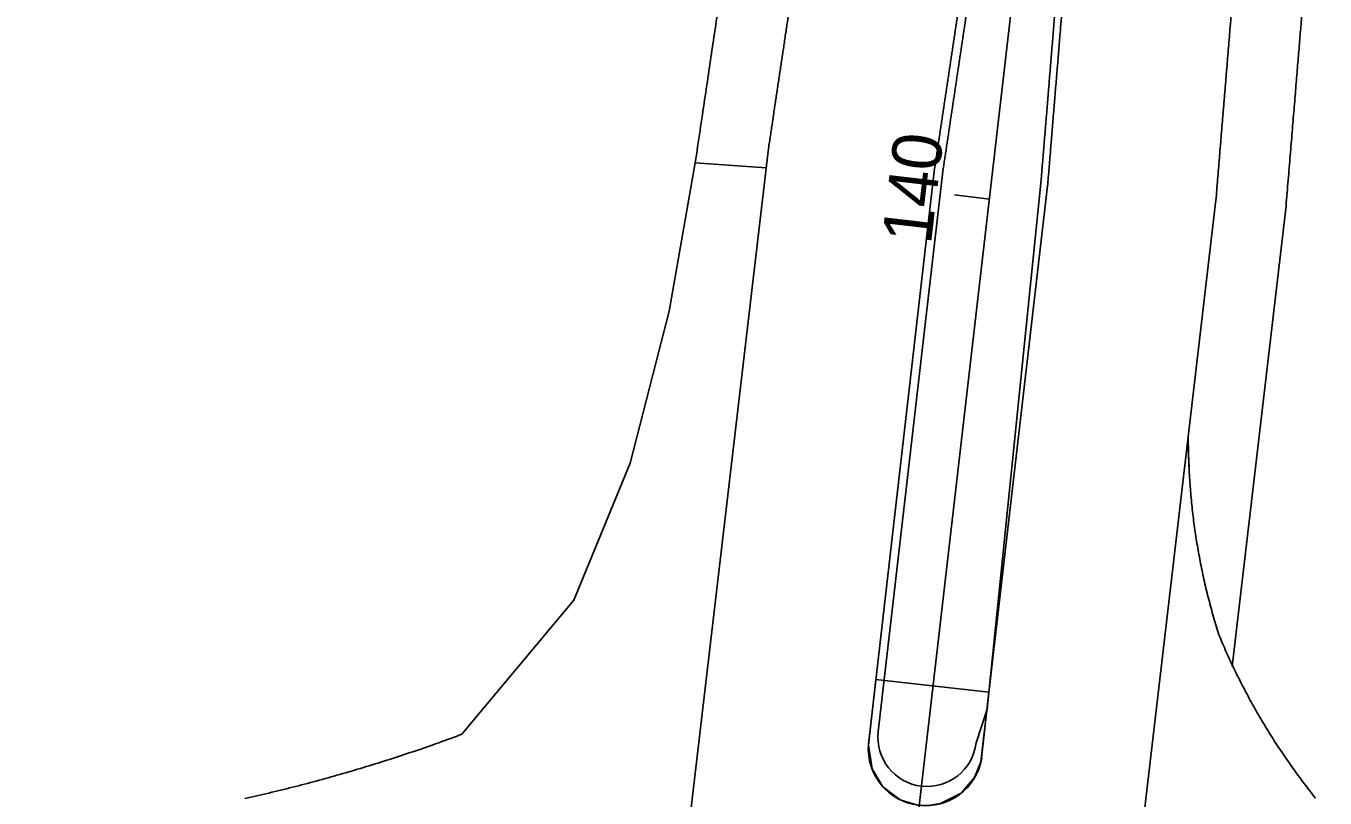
# Model space of a CAD drawing. Extents: x 2318076 to 2324211, y 613525 to 629939.
# Drawn here: x 2320485.2 to 2320669.8, y 628482.6 to 628592.3 of the extents above; entities that cross this region are included whole.
import ezdxf

# ---------------------------------------------------------------- set-up
doc = ezdxf.new("R2010")
doc.units = 0
for name, color, linetype in [('Default', 7, 'Continuous'), ('GE_P_CL_50', 7, 'Continuous'), ('PM_P_Island', 7, 'Continuous'), ('PV_P_EOP', 7, 'Continuous'), ('PV_P_Shoulder', 7, 'Continuous'), ('PV_X_Curb', 7, 'Continuous'), ('RS_Raster1', 7, 'Continuous')]:
    doc.layers.add(name, color=color, linetype=linetype)

msp = doc.modelspace()

# ---------------------------------------------------------------- linework, layer by layer
at = {"layer": 'Default'}
msp.add_line((2320580.32, 628572.84), (2320590.42, 628572.16), dxfattribs=at)
at = {"layer": 'GE_P_CL_50'}
msp.add_line((2320622.12, 628567.72), (2320617.15, 628568.29), dxfattribs=at)
msp.add_lwpolyline([(2320485.22, 627375.57), (2320502.11, 627520.92), (2320519.22, 627676.47), (2320531.82, 627783.89), (2320546.8, 627927.12), (2320554.45, 627991.34), (2320572.51, 628138.41), (2320649.52, 628804.84), (2320678.77, 629064.5), (2320690.76, 629163.78), (2320713.75, 629362.45), (2320725.26, 629461.78), (2320736.97, 629561.09), (2320748.4, 629660.43), (2320759.09, 629759.86), (2320769.62, 629859.3), (2320777.51, 629931.12), (2320778.25, 629937.84)], dxfattribs=at)
at = {"layer": 'PM_P_Island'}
msp.add_lwpolyline([(2320622.04, 628497.59), (2320606, 628499.42), (2320604.93, 628490.08), (2320605.45, 628486.7), (2320606.99, 628484.17), (2320609.45, 628482.31), (2320611.9, 628481.55), (2320612.52, 628481.49), (2320613.49, 628481.49), (2320615.17, 628481.76), (2320618.12, 628483.27), (2320620.03, 628485.47), (2320620.95, 628487.79)], close=True, dxfattribs=at)
at = {"layer": 'PV_P_EOP'}
for p, q in [((2320590.74, 628574.92), (2320513.05, 627912.02)), ((2320604.94, 628490.2), (2320614.34, 628572.05)), ((2320620.93, 628487.71), (2320630.4, 628569.61)), ((2320576.7, 627905.37), (2320654.32, 628567.57))]:
    msp.add_line(p, q, dxfattribs=at)
for points in [[(2320650.31, 628533.42), (2320650.52, 628529.13), (2320650.53, 628528.81), (2320650.55, 628528.48), (2320650.57, 628528.15), (2320650.59, 628527.83), (2320650.61, 628527.5), (2320650.64, 628527.18), (2320650.66, 628526.85), (2320650.68, 628526.53), (2320650.71, 628526.2), (2320650.74, 628525.88), (2320650.77, 628525.55), (2320650.8, 628525.23), (2320650.83, 628524.9), (2320650.86, 628524.58), (2320650.89, 628524.26), (2320650.92, 628523.93), (2320650.96, 628523.61), (2320651, 628523.28), (2320651.03, 628522.96), (2320651.07, 628522.64), (2320651.11, 628522.31), (2320651.15, 628521.99), (2320651.19, 628521.67), (2320651.24, 628521.34), (2320651.28, 628521.02), (2320651.33, 628520.7), (2320651.37, 628520.37), (2320651.42, 628520.05), (2320651.47, 628519.73), (2320651.52, 628519.41), (2320651.57, 628519.09), (2320651.62, 628518.76), (2320651.68, 628518.44), (2320651.73, 628518.12), (2320651.79, 628517.8), (2320651.84, 628517.48), (2320651.9, 628517.16), (2320651.96, 628516.84), (2320652.02, 628516.52), (2320652.08, 628516.2), (2320652.14, 628515.88), (2320652.21, 628515.56), (2320652.27, 628515.24), (2320652.34, 628514.92), (2320652.4, 628514.6), (2320652.47, 628514.28), (2320652.54, 628513.96), (2320652.61, 628513.64), (2320652.68, 628513.33), (2320652.76, 628513.01), (2320652.83, 628512.69), (2320652.9, 628512.37), (2320652.98, 628512.06), (2320653.06, 628511.74), (2320653.13, 628511.42), (2320653.21, 628511.11), (2320653.29, 628510.79), (2320653.38, 628510.48), (2320653.46, 628510.16), (2320653.54, 628509.85), (2320653.63, 628509.53), (2320653.71, 628509.22), (2320653.8, 628508.9), (2320653.89, 628508.59), (2320653.98, 628508.28), (2320654.07, 628507.96), (2320654.16, 628507.65), (2320654.25, 628507.34), (2320654.34, 628507.03), (2320654.44, 628506.71), (2320654.54, 628506.4), (2320654.63, 628506.09), (2320654.73, 628505.78)], [(2320654.73, 628505.78), (2320654.86, 628505.47), (2320654.99, 628505.16), (2320655.12, 628504.86), (2320655.25, 628504.55), (2320655.38, 628504.24), (2320655.52, 628503.94), (2320655.65, 628503.63), (2320655.79, 628503.32), (2320655.92, 628503.02), (2320656.06, 628502.71), (2320656.2, 628502.41), (2320656.34, 628502.11), (2320656.48, 628501.8), (2320656.62, 628501.5), (2320656.77, 628501.2), (2320656.91, 628500.9), (2320657.06, 628500.6), (2320657.2, 628500.3), (2320657.35, 628500), (2320657.5, 628499.7), (2320657.65, 628499.4), (2320657.8, 628499.1), (2320657.95, 628498.8), (2320658.1, 628498.51), (2320658.26, 628498.21), (2320658.41, 628497.91), (2320658.57, 628497.62), (2320658.73, 628497.32), (2320658.88, 628497.03), (2320659.04, 628496.73), (2320659.2, 628496.44), (2320659.36, 628496.15), (2320659.52, 628495.85), (2320659.69, 628495.56), (2320659.85, 628495.27), (2320660.02, 628494.98), (2320660.18, 628494.69), (2320660.35, 628494.4), (2320660.52, 628494.11), (2320660.69, 628493.82), (2320660.86, 628493.54), (2320661.03, 628493.25), (2320661.2, 628492.96), (2320661.37, 628492.68), (2320661.55, 628492.39), (2320661.72, 628492.11), (2320661.9, 628491.82), (2320662.08, 628491.54), (2320662.25, 628491.26), (2320662.43, 628490.98), (2320662.61, 628490.69), (2320662.79, 628490.41), (2320662.98, 628490.13), (2320663.16, 628489.85), (2320663.34, 628489.57), (2320663.53, 628489.3), (2320663.71, 628489.02), (2320663.9, 628488.74), (2320664.09, 628488.47), (2320664.28, 628488.19), (2320664.47, 628487.91), (2320664.66, 628487.64), (2320664.85, 628487.37), (2320665.04, 628487.09), (2320665.24, 628486.82), (2320665.43, 628486.55), (2320665.63, 628486.28), (2320665.82, 628486.01), (2320666.02, 628485.74), (2320666.22, 628485.47), (2320666.42, 628485.2), (2320666.62, 628484.93), (2320666.82, 628484.67), (2320667.02, 628484.4), (2320667.22, 628484.14), (2320667.43, 628483.87), (2320667.63, 628483.61), (2320667.84, 628483.35), (2320668.04, 628483.08), (2320668.25, 628482.82), (2320668.46, 628482.56)]]:
    msp.add_lwpolyline(points, dxfattribs=at)
msp.add_arc((2320613.03, 628489.59), 8.12, 175.7115, 350.2041, dxfattribs=at)
for points in [[(2320590.74, 628574.92), (2320590.87, 628575.82), (2320591.01, 628576.72), (2320591.14, 628577.62), (2320591.28, 628578.53), (2320591.41, 628579.43), (2320591.54, 628580.33), (2320591.68, 628581.23), (2320591.81, 628582.13), (2320591.95, 628583.04), (2320592.08, 628583.94), (2320592.22, 628584.84), (2320592.35, 628585.74), (2320592.49, 628586.64), (2320592.62, 628587.55), (2320592.76, 628588.45), (2320592.89, 628589.35), (2320593.02, 628590.25), (2320593.16, 628591.15), (2320593.29, 628592.06), (2320593.43, 628592.96), (2320593.56, 628593.86), (2320593.7, 628594.76), (2320593.83, 628595.66), (2320593.97, 628596.57), (2320594.1, 628597.47), (2320594.23, 628598.37), (2320594.37, 628599.27), (2320594.5, 628600.17), (2320594.64, 628601.07), (2320594.77, 628601.98), (2320594.91, 628602.88), (2320595.04, 628603.78), (2320595.18, 628604.68), (2320595.31, 628605.58), (2320595.44, 628606.49), (2320595.58, 628607.39), (2320595.71, 628608.29), (2320595.85, 628609.19), (2320595.98, 628610.09), (2320596.12, 628611), (2320596.25, 628611.9), (2320596.39, 628612.8), (2320596.52, 628613.7), (2320596.65, 628614.6), (2320596.79, 628615.51), (2320596.92, 628616.41), (2320597.06, 628617.31), (2320597.19, 628618.21), (2320597.33, 628619.11), (2320597.46, 628620.02), (2320597.6, 628620.92), (2320597.73, 628621.82), (2320597.86, 628622.72), (2320598, 628623.62), (2320598.13, 628624.53), (2320598.27, 628625.43), (2320598.4, 628626.33), (2320598.54, 628627.23), (2320598.67, 628628.13), (2320598.81, 628629.03), (2320598.94, 628629.94), (2320599.07, 628630.84), (2320599.21, 628631.74), (2320599.34, 628632.64), (2320599.48, 628633.54), (2320599.61, 628634.45), (2320599.75, 628635.35), (2320599.88, 628636.25), (2320600.02, 628637.15), (2320600.15, 628638.05), (2320600.28, 628638.96), (2320600.42, 628639.86), (2320600.55, 628640.76), (2320600.69, 628641.66)], [(2320654.32, 628567.57), (2320654.39, 628568.48), (2320654.46, 628569.39), (2320654.54, 628570.3), (2320654.61, 628571.21), (2320654.69, 628572.12), (2320654.76, 628573.02), (2320654.84, 628573.93), (2320654.91, 628574.84), (2320654.99, 628575.75), (2320655.06, 628576.66), (2320655.14, 628577.57), (2320655.21, 628578.48), (2320655.29, 628579.39), (2320655.36, 628580.3), (2320655.44, 628581.2), (2320655.51, 628582.11), (2320655.59, 628583.02), (2320655.66, 628583.93), (2320655.74, 628584.84), (2320655.81, 628585.75), (2320655.89, 628586.66), (2320655.96, 628587.57), (2320656.04, 628588.48), (2320656.11, 628589.38), (2320656.18, 628590.29), (2320656.26, 628591.2), (2320656.33, 628592.11), (2320656.41, 628593.02), (2320656.48, 628593.93), (2320656.56, 628594.84), (2320656.63, 628595.75), (2320656.71, 628596.65), (2320656.78, 628597.56), (2320656.86, 628598.47), (2320656.93, 628599.38), (2320657.01, 628600.29), (2320657.08, 628601.2), (2320657.16, 628602.11), (2320657.23, 628603.02), (2320657.31, 628603.93), (2320657.38, 628604.83), (2320657.46, 628605.74), (2320657.53, 628606.65), (2320657.61, 628607.56), (2320657.68, 628608.47), (2320657.76, 628609.38), (2320657.83, 628610.29), (2320657.91, 628611.2), (2320657.98, 628612.1), (2320658.05, 628613.01), (2320658.13, 628613.92), (2320658.2, 628614.83), (2320658.28, 628615.74), (2320658.35, 628616.65), (2320658.43, 628617.56), (2320658.5, 628618.47), (2320658.58, 628619.38), (2320658.65, 628620.28), (2320658.73, 628621.19), (2320658.8, 628622.1), (2320658.88, 628623.01), (2320658.95, 628623.92), (2320659.03, 628624.83), (2320659.1, 628625.74), (2320659.18, 628626.65), (2320659.25, 628627.55), (2320659.33, 628628.46), (2320659.4, 628629.37), (2320659.48, 628630.28), (2320659.55, 628631.19), (2320659.63, 628632.1), (2320659.7, 628633.01), (2320659.77, 628633.92), (2320659.85, 628634.83)], [(2320614.34, 628572.05), (2320614.46, 628572.85), (2320614.58, 628573.65), (2320614.7, 628574.46), (2320614.82, 628575.26), (2320614.94, 628576.06), (2320615.06, 628576.86), (2320615.18, 628577.67), (2320615.3, 628578.47), (2320615.42, 628579.27), (2320615.54, 628580.07), (2320615.66, 628580.87), (2320615.78, 628581.68), (2320615.9, 628582.48), (2320616.02, 628583.28), (2320616.14, 628584.08), (2320616.26, 628584.89), (2320616.38, 628585.69), (2320616.5, 628586.49), (2320616.62, 628587.29), (2320616.74, 628588.1), (2320616.86, 628588.9), (2320616.98, 628589.7), (2320617.1, 628590.5), (2320617.22, 628591.31), (2320617.34, 628592.11), (2320617.46, 628592.91), (2320617.58, 628593.71), (2320617.69, 628594.51), (2320617.81, 628595.32), (2320617.93, 628596.12), (2320618.05, 628596.92), (2320618.17, 628597.72), (2320618.29, 628598.53), (2320618.41, 628599.33), (2320618.53, 628600.13), (2320618.65, 628600.93), (2320618.77, 628601.74), (2320618.89, 628602.54), (2320619.01, 628603.34), (2320619.13, 628604.14), (2320619.25, 628604.95), (2320619.37, 628605.75), (2320619.49, 628606.55), (2320619.61, 628607.35), (2320619.73, 628608.15), (2320619.85, 628608.96), (2320619.97, 628609.76), (2320620.09, 628610.56), (2320620.21, 628611.36), (2320620.33, 628612.17), (2320620.45, 628612.97), (2320620.57, 628613.77), (2320620.69, 628614.57), (2320620.81, 628615.38), (2320620.93, 628616.18), (2320621.05, 628616.98), (2320621.17, 628617.78), (2320621.29, 628618.58), (2320621.41, 628619.39), (2320621.53, 628620.19), (2320621.65, 628620.99), (2320621.77, 628621.79), (2320621.89, 628622.6), (2320622.01, 628623.4), (2320622.13, 628624.2), (2320622.25, 628625), (2320622.37, 628625.81), (2320622.49, 628626.61), (2320622.61, 628627.41), (2320622.73, 628628.21), (2320622.85, 628629.02), (2320622.97, 628629.82), (2320623.21, 628631.42)], [(2320630.4, 628569.61), (2320630.46, 628570.42), (2320630.53, 628571.23), (2320630.6, 628572.04), (2320630.66, 628572.85), (2320630.73, 628573.66), (2320630.8, 628574.47), (2320630.86, 628575.27), (2320630.93, 628576.08), (2320630.99, 628576.89), (2320631.06, 628577.7), (2320631.13, 628578.51), (2320631.19, 628579.32), (2320631.26, 628580.13), (2320631.33, 628580.93), (2320631.39, 628581.74), (2320631.46, 628582.55), (2320631.52, 628583.36), (2320631.59, 628584.17), (2320631.66, 628584.98), (2320631.72, 628585.79), (2320631.79, 628586.59), (2320631.86, 628587.4), (2320631.92, 628588.21), (2320631.99, 628589.02), (2320632.05, 628589.83), (2320632.12, 628590.64), (2320632.19, 628591.44), (2320632.25, 628592.25), (2320632.32, 628593.06), (2320632.38, 628593.87), (2320632.45, 628594.68), (2320632.52, 628595.49), (2320632.58, 628596.3), (2320632.65, 628597.1), (2320632.72, 628597.91), (2320632.78, 628598.72), (2320632.85, 628599.53), (2320632.91, 628600.34), (2320632.98, 628601.15), (2320633.05, 628601.96), (2320633.11, 628602.76), (2320633.18, 628603.57), (2320633.25, 628604.38), (2320633.31, 628605.19), (2320633.38, 628606), (2320633.44, 628606.81), (2320633.51, 628607.62), (2320633.58, 628608.42), (2320633.64, 628609.23), (2320633.71, 628610.04), (2320633.78, 628610.85), (2320633.84, 628611.66), (2320633.91, 628612.47), (2320633.97, 628613.28), (2320634.04, 628614.08), (2320634.11, 628614.89), (2320634.17, 628615.7), (2320634.24, 628616.51), (2320634.31, 628617.32), (2320634.37, 628618.13), (2320634.44, 628618.94), (2320634.5, 628619.74), (2320634.57, 628620.55), (2320634.64, 628621.36), (2320634.7, 628622.17), (2320634.77, 628622.98), (2320634.84, 628623.79), (2320634.9, 628624.6), (2320634.97, 628625.4), (2320635.03, 628626.21), (2320635.1, 628627.02), (2320635.17, 628627.83), (2320635.3, 628629.45)]]:
    msp.add_spline(points, degree=3, dxfattribs=at)
at = {"layer": 'PV_P_Shoulder'}
msp.add_line((2320656.61, 628501.27), (2320664.28, 628566.75), dxfattribs=at)
for points in [[(2320580.32, 628572.84), (2320584.16, 628598.64), (2320587.48, 628620.89), (2320590.8, 628643.14)], [(2320664.28, 628566.75), (2320666.13, 628589.17), (2320667.97, 628611.59), (2320669.82, 628634.01)]]:
    msp.add_open_spline(points, degree=2, dxfattribs=at)
at = {"layer": 'PV_X_Curb'}
msp.add_line((2320606.32, 628492), (2320615.57, 628572.05), dxfattribs=at)
msp.add_lwpolyline([(2320620.23, 628490.39), (2320621.8, 628495.17), (2320629.48, 628570.44)], dxfattribs=at)
for start, end in [(173.4084, 263.4084), (263.4084, 353.4084)]:
    msp.add_arc((2320613.28, 628491.2), 7, start, end, dxfattribs=at)
for points in [[(2320615.57, 628572.05), (2320615.69, 628572.85), (2320615.81, 628573.65), (2320615.93, 628574.46), (2320616.05, 628575.26), (2320616.17, 628576.06), (2320616.29, 628576.86), (2320616.41, 628577.67), (2320616.53, 628578.47), (2320616.65, 628579.27), (2320616.77, 628580.07), (2320616.89, 628580.87), (2320617.01, 628581.68), (2320617.13, 628582.48), (2320617.25, 628583.28), (2320617.37, 628584.08), (2320617.49, 628584.89), (2320617.61, 628585.69), (2320617.73, 628586.49), (2320617.85, 628587.29), (2320617.97, 628588.1), (2320618.09, 628588.9), (2320618.21, 628589.7), (2320618.33, 628590.5), (2320618.45, 628591.31), (2320618.57, 628592.11), (2320618.69, 628592.91), (2320618.81, 628593.71), (2320618.93, 628594.51), (2320619.05, 628595.32), (2320619.17, 628596.12), (2320619.29, 628596.92), (2320619.41, 628597.72), (2320619.53, 628598.53), (2320619.65, 628599.33), (2320619.77, 628600.13), (2320619.89, 628600.93), (2320620.01, 628601.74), (2320620.13, 628602.54), (2320620.25, 628603.34), (2320620.37, 628604.14), (2320620.49, 628604.95), (2320620.61, 628605.75), (2320620.73, 628606.55), (2320620.85, 628607.35), (2320620.97, 628608.15), (2320621.09, 628608.96), (2320621.21, 628609.76), (2320621.33, 628610.56), (2320621.45, 628611.36), (2320621.57, 628612.17), (2320621.69, 628612.97), (2320621.81, 628613.77), (2320621.93, 628614.57), (2320622.05, 628615.38), (2320622.17, 628616.18), (2320622.29, 628616.98), (2320622.41, 628617.78), (2320622.53, 628618.58), (2320622.65, 628619.39), (2320622.77, 628620.19), (2320622.89, 628620.99), (2320623.01, 628621.79), (2320623.13, 628622.6), (2320623.25, 628623.4), (2320623.37, 628624.2), (2320623.49, 628625), (2320623.61, 628625.81), (2320623.73, 628626.61), (2320623.85, 628627.41), (2320623.97, 628628.21), (2320624.09, 628629.02), (2320624.21, 628629.82), (2320623.32, 628632.14), (2320623.12, 628630.84)], [(2320629.48, 628570.44), (2320629.55, 628571.25), (2320629.61, 628572.06), (2320629.68, 628572.87), (2320629.75, 628573.68), (2320629.81, 628574.48), (2320629.88, 628575.29), (2320629.94, 628576.1), (2320630.01, 628576.91), (2320630.08, 628577.72), (2320630.14, 628578.53), (2320630.21, 628579.34), (2320630.28, 628580.14), (2320630.34, 628580.95), (2320630.41, 628581.76), (2320630.47, 628582.57), (2320630.54, 628583.38), (2320630.61, 628584.19), (2320630.67, 628585), (2320630.74, 628585.8), (2320630.8, 628586.61), (2320630.87, 628587.42), (2320630.94, 628588.23), (2320631, 628589.04), (2320631.07, 628589.85), (2320631.14, 628590.66), (2320631.2, 628591.46), (2320631.27, 628592.27), (2320631.33, 628593.08), (2320631.4, 628593.89), (2320631.47, 628594.7), (2320631.53, 628595.51), (2320631.6, 628596.32), (2320631.67, 628597.12), (2320631.73, 628597.93), (2320631.8, 628598.74), (2320631.86, 628599.55), (2320631.93, 628600.36), (2320632, 628601.17), (2320632.06, 628601.98), (2320632.13, 628602.78), (2320632.2, 628603.59), (2320632.26, 628604.4), (2320632.33, 628605.21), (2320632.39, 628606.02), (2320632.46, 628606.83), (2320632.53, 628607.64), (2320632.59, 628608.44), (2320632.66, 628609.25), (2320632.73, 628610.06), (2320632.79, 628610.87), (2320632.86, 628611.68), (2320632.92, 628612.49), (2320632.99, 628613.3), (2320633.06, 628614.1), (2320633.12, 628614.91), (2320633.19, 628615.72), (2320633.26, 628616.53), (2320633.32, 628617.34), (2320633.39, 628618.15), (2320633.45, 628618.95), (2320633.52, 628619.76), (2320633.59, 628620.57), (2320633.65, 628621.38), (2320633.72, 628622.19), (2320633.79, 628623), (2320633.85, 628623.81), (2320633.92, 628624.61), (2320633.98, 628625.42), (2320634.05, 628626.23), (2320634.12, 628627.04), (2320634.18, 628627.85), (2320634.25, 628628.66), (2320634.38, 628630.27)]]:
    msp.add_spline(points, degree=3, dxfattribs=at)
at = {"layer": 'RS_Raster1'}
for points in [[(2320547.18, 628491.63), (2320563.05, 628510.71), (2320571.06, 628530.15), (2320576.64, 628551.77), (2320580.32, 628572.84)], [(2320650.37, 628533.94), (2320650.43, 628531.41), (2320650.44, 628531.09), (2320650.45, 628530.76), (2320650.46, 628530.43), (2320650.47, 628530.11), (2320650.49, 628529.78), (2320650.5, 628529.46), (2320650.52, 628529.13), (2320650.53, 628528.81), (2320650.55, 628528.48), (2320650.57, 628528.15), (2320650.59, 628527.83), (2320650.61, 628527.5), (2320650.64, 628527.18), (2320650.66, 628526.85), (2320650.68, 628526.53), (2320650.71, 628526.2), (2320650.74, 628525.88), (2320650.77, 628525.55), (2320650.8, 628525.23), (2320650.83, 628524.9), (2320650.86, 628524.58), (2320650.89, 628524.26), (2320650.92, 628523.93), (2320650.96, 628523.61), (2320651, 628523.28), (2320651.03, 628522.96), (2320651.07, 628522.64), (2320651.11, 628522.31), (2320651.15, 628521.99), (2320651.19, 628521.67), (2320651.24, 628521.34), (2320651.28, 628521.02), (2320651.33, 628520.7), (2320651.37, 628520.37), (2320651.42, 628520.05), (2320651.47, 628519.73), (2320651.52, 628519.41), (2320651.57, 628519.09), (2320651.62, 628518.76), (2320651.68, 628518.44), (2320651.73, 628518.12), (2320651.79, 628517.8), (2320651.84, 628517.48), (2320651.9, 628517.16), (2320651.96, 628516.84), (2320652.02, 628516.52), (2320652.08, 628516.2), (2320652.14, 628515.88), (2320652.21, 628515.56), (2320652.27, 628515.24), (2320652.34, 628514.92), (2320652.4, 628514.6), (2320652.47, 628514.28), (2320652.54, 628513.96), (2320652.61, 628513.64), (2320652.68, 628513.33), (2320652.76, 628513.01), (2320652.83, 628512.69), (2320652.9, 628512.37), (2320652.98, 628512.06), (2320653.06, 628511.74), (2320653.13, 628511.42), (2320653.21, 628511.11), (2320653.29, 628510.79), (2320653.38, 628510.48), (2320653.46, 628510.16), (2320653.54, 628509.85), (2320653.63, 628509.53), (2320653.71, 628509.22), (2320653.8, 628508.9), (2320653.89, 628508.59), (2320653.98, 628508.28), (2320654.07, 628507.96), (2320654.16, 628507.65), (2320654.25, 628507.34), (2320654.34, 628507.03), (2320654.44, 628506.71), (2320654.54, 628506.4), (2320654.63, 628506.09), (2320654.73, 628505.78)], [(2320654.73, 628505.78), (2320654.86, 628505.47), (2320654.99, 628505.16), (2320655.12, 628504.86), (2320655.25, 628504.55), (2320655.38, 628504.24), (2320655.52, 628503.94), (2320655.65, 628503.63), (2320655.79, 628503.32), (2320655.92, 628503.02), (2320656.06, 628502.71), (2320656.2, 628502.41), (2320656.34, 628502.11), (2320656.48, 628501.8), (2320656.62, 628501.5), (2320656.77, 628501.2), (2320656.91, 628500.9), (2320657.06, 628500.6), (2320657.2, 628500.3), (2320657.35, 628500), (2320657.5, 628499.7), (2320657.65, 628499.4), (2320657.8, 628499.1), (2320657.95, 628498.8), (2320658.1, 628498.51), (2320658.26, 628498.21), (2320658.41, 628497.91), (2320658.57, 628497.62), (2320658.73, 628497.32), (2320658.88, 628497.03), (2320659.04, 628496.73), (2320659.2, 628496.44), (2320659.36, 628496.15), (2320659.52, 628495.85), (2320659.69, 628495.56), (2320659.85, 628495.27), (2320660.02, 628494.98), (2320660.18, 628494.69), (2320660.35, 628494.4), (2320660.52, 628494.11), (2320660.69, 628493.82), (2320660.86, 628493.54), (2320661.03, 628493.25), (2320661.2, 628492.96), (2320661.37, 628492.68), (2320661.55, 628492.39), (2320661.72, 628492.11), (2320661.9, 628491.82), (2320662.08, 628491.54), (2320662.25, 628491.26), (2320662.43, 628490.98), (2320662.61, 628490.69), (2320662.79, 628490.41), (2320662.98, 628490.13), (2320663.16, 628489.85), (2320663.34, 628489.57), (2320663.53, 628489.3), (2320663.71, 628489.02), (2320663.9, 628488.74), (2320664.09, 628488.47), (2320664.28, 628488.19), (2320664.47, 628487.91), (2320664.66, 628487.64), (2320664.85, 628487.37), (2320665.04, 628487.09), (2320665.24, 628486.82), (2320665.43, 628486.55), (2320665.63, 628486.28), (2320665.82, 628486.01), (2320666.02, 628485.74), (2320666.22, 628485.47), (2320666.42, 628485.2), (2320666.62, 628484.93), (2320666.82, 628484.67), (2320667.02, 628484.4), (2320667.22, 628484.14), (2320667.43, 628483.87), (2320667.63, 628483.61), (2320667.84, 628483.35), (2320668.04, 628483.08), (2320668.25, 628482.82), (2320668.46, 628482.56)], [(2320516.33, 628482.49), (2320516.75, 628482.58), (2320517.18, 628482.68), (2320517.6, 628482.77), (2320518.03, 628482.87), (2320518.45, 628482.97), (2320518.87, 628483.07), (2320519.3, 628483.17), (2320519.72, 628483.27), (2320520.15, 628483.37), (2320520.57, 628483.47), (2320520.99, 628483.57), (2320521.41, 628483.67), (2320521.84, 628483.78), (2320522.26, 628483.88), (2320522.68, 628483.99), (2320523.1, 628484.1), (2320523.53, 628484.2), (2320523.95, 628484.31), (2320524.37, 628484.42), (2320524.79, 628484.53), (2320525.21, 628484.64), (2320525.63, 628484.75), (2320526.05, 628484.86), (2320526.47, 628484.98), (2320526.89, 628485.09), (2320527.31, 628485.2), (2320527.73, 628485.32), (2320528.15, 628485.44), (2320528.57, 628485.55), (2320528.99, 628485.67), (2320529.41, 628485.79), (2320529.83, 628485.91), (2320530.24, 628486.03), (2320530.66, 628486.15), (2320531.08, 628486.27), (2320531.5, 628486.39), (2320531.92, 628486.52), (2320532.33, 628486.64), (2320532.75, 628486.77), (2320533.17, 628486.89), (2320533.58, 628487.02), (2320534, 628487.14), (2320534.41, 628487.27), (2320534.83, 628487.4), (2320535.25, 628487.53), (2320535.66, 628487.66), (2320536.08, 628487.79), (2320536.49, 628487.92), (2320536.9, 628488.06), (2320537.32, 628488.19), (2320537.73, 628488.33), (2320538.15, 628488.46), (2320538.56, 628488.6), (2320538.97, 628488.73), (2320539.39, 628488.87), (2320539.8, 628489.01), (2320540.21, 628489.15), (2320540.62, 628489.29), (2320541.04, 628489.43), (2320541.45, 628489.57), (2320541.86, 628489.71), (2320542.27, 628489.85), (2320542.68, 628490), (2320543.09, 628490.14), (2320543.5, 628490.29), (2320543.91, 628490.43), (2320544.32, 628490.58), (2320544.73, 628490.73), (2320545.14, 628490.88), (2320545.55, 628491.03), (2320545.96, 628491.18), (2320546.36, 628491.33), (2320546.77, 628491.48), (2320547.18, 628491.63)]]:
    msp.add_lwpolyline(points, dxfattribs=at)

# ---------------------------------------------------------------- texts
at = {"layer": 'GE_P_CL_50'}
msp.add_text('140', height=7, rotation=83.4084, dxfattribs=at).set_placement((2320613.81, 628561.14))

doc.saveas('drawing.dxf')
